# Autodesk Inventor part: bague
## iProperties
Created: 2001-10
Part Number: bague
Material: Par défaut
Document SubType Name: Modélisation
Control State: 0
Master: False
Checked Out: False
Shininess: 20.0
Length Units: 11269
Angle Units: 11279
Time Units: 11290
Mass Units: 11283
Length Display Precision: 3
Angle Display Precision: 2
Density: 0.0
Volumn: 0.0
Area: 0.0
PropertySet Name: Model Information
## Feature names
1. Révolution1 [Revolution]
2. Perçage1 [Hole]
